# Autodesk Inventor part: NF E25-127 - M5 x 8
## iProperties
Library Location: C:\Program Files\Autodesk\Inventor 6\content
Library: local
SubLibrary: AFNOR
Family: 20
Member: 470
Member Major Revision: 1
Member Minor Revision: 1
Comments: To add or edit properties for Autodesk Inventor files, use iProperties.
Created: 2004-05
Part Number: NF E25-127 - M5 x 8
Vendor: Autodesk Inc.
Document SubType Name: Modeling
Designer: David
Description: Vis à tête cylindrique fendue
Standard: NF E25-127 M5 x 8
Alert: To add or edit properties for Autodesk Inventor files, use iProperties.
Control State: 0
Master: False
Checked Out: False
Shininess: 64.0
Length Units: 11269
Angle Units: 11279
Time Units: 11290
Mass Units: 11283
Length Display Precision: 3
Angle Display Precision: 2
Compacted: True
EGR: 1
Density: 0.0
Volumn: 0.0
Area: 0.0
PropertySet Name: Model Information
Author: David
Revision Number: 1
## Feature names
1. Corps [Revolution]
2. Congé1 [Fillet]
3. Fente [Extrusion]
4. Chanfrein1 [Chamfer]
